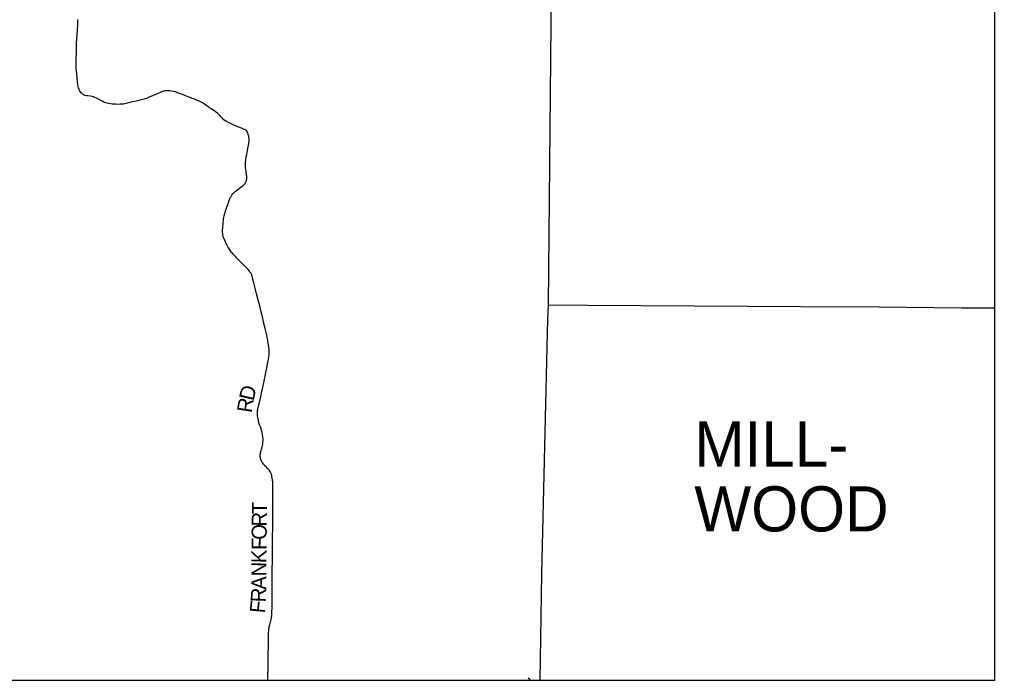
# Model space of a CAD drawing. Extents: x -29.6 to 34, y 0 to 22.
# Drawn here: x -14.201 to -10.748, y 1.053 to 3.392 of the extents above; entities that cross this region are included whole.
import ezdxf

# ---------------------------------------------------------------- set-up
doc = ezdxf.new("R2010")
doc.units = 0
for name, color, linetype in [('GM_X_County_Road', 7, 'Continuous'), ('GM_X_County_Road_Text', 7, 'Continuous'), ('GM_X_Minor_River', 7, 'Continuous'), ('GM_X_Township', 7, 'Continuous'), ('GM_X_Township_Text', 7, 'Continuous'), ('SH_Text', 7, 'Continuous')]:
    doc.layers.add(name, color=color, linetype=linetype)

msp = doc.modelspace()

# ---------------------------------------------------------------- linework, layer by layer
at = {"layer": 'GM_X_County_Road'}
for points in [[(-13.9953, 3.376), (-13.9945, 3.3926)], [(-13.4013, 3.0017), (-13.4052, 3.0035), (-13.4149, 3.0076), (-13.4337, 3.0154), (-13.4492, 3.022), (-13.4588, 3.0263), (-13.4656, 3.0297), (-13.4697, 3.0321), (-13.4731, 3.0343), (-13.4773, 3.0375), (-13.4786, 3.0386), (-13.4828, 3.0427), (-13.4848, 3.0448), (-13.4886, 3.0492), (-13.4919, 3.053), (-13.4938, 3.055), (-13.4976, 3.0584), (-13.5002, 3.0605), (-13.5067, 3.0653), (-13.5081, 3.0663), (-13.5133, 3.0699), (-13.5219, 3.0759), (-13.5243, 3.0775), (-13.5262, 3.0788), (-13.5281, 3.0802), (-13.5305, 3.0818), (-13.5381, 3.0872), (-13.5461, 3.0929), (-13.5529, 3.0973), (-13.5598, 3.1012), (-13.5651, 3.1038), (-13.5679, 3.1049), (-13.5744, 3.1073), (-13.5815, 3.11), (-13.5841, 3.1111), (-13.5852, 3.1116), (-13.5895, 3.1133), (-13.5911, 3.1139), (-13.5921, 3.1142), (-13.6003, 3.1173), (-13.6134, 3.1224), (-13.6177, 3.1241), (-13.6405, 3.1328), (-13.6504, 3.1362), (-13.6559, 3.1378), (-13.6626, 3.1393), (-13.6683, 3.1401), (-13.6735, 3.1403), (-13.6781, 3.1403), (-13.6827, 3.14), (-13.6866, 3.1396), (-13.6915, 3.1383), (-13.7006, 3.1353), (-13.7163, 3.1284), (-13.7258, 3.1242), (-13.7304, 3.1222), (-13.7336, 3.1207), (-13.7415, 3.1172), (-13.7491, 3.1142), (-13.7562, 3.1117), (-13.7641, 3.1094), (-13.7743, 3.1067), (-13.7931, 3.1028), (-13.8015, 3.1007), (-13.81, 3.0986), (-13.8184, 3.0965), (-13.8279, 3.0942), (-13.8331, 3.0933), (-13.8394, 3.0925), (-13.8447, 3.0922), (-13.8546, 3.092), (-13.8616, 3.0922), (-13.8732, 3.0929), (-13.879, 3.0936), (-13.8866, 3.0949), (-13.8911, 3.096), (-13.8973, 3.0979), (-13.9022, 3.0999), (-13.9091, 3.1032), (-13.929, 3.1142), (-13.9342, 3.1167), (-13.939, 3.1185), (-13.9434, 3.1196), (-13.9502, 3.1206), (-13.9588, 3.1217), (-13.9641, 3.1227), (-13.9686, 3.1239), (-13.972, 3.1252), (-13.9746, 3.1266), (-13.9777, 3.1285), (-13.9804, 3.1308), (-13.9829, 3.1334), (-13.9854, 3.1367), (-13.9885, 3.1417), (-13.9905, 3.146), (-13.9919, 3.1499), (-13.9935, 3.1561), (-13.9945, 3.1613), (-13.996, 3.1734), (-13.9986, 3.1999), (-13.9996, 3.2103), (-14.0003, 3.2201), (-14.0005, 3.2276), (-14.0005, 3.2432), (-14.0002, 3.2587), (-13.9999, 3.2703), (-13.9997, 3.2859), (-13.999, 3.3068), (-13.9982, 3.3236), (-13.9974, 3.3387), (-13.9965, 3.3538), (-13.9953, 3.376)], [(-13.4323, 2.5493), (-13.4352, 2.5522), (-13.4444, 2.5619), (-13.4482, 2.5661), (-13.45, 2.5682), (-13.4539, 2.5734), (-13.4581, 2.5795), (-13.4619, 2.5857), (-13.4668, 2.5948), (-13.4712, 2.6036), (-13.4722, 2.6059), (-13.4758, 2.6141), (-13.4778, 2.619), (-13.4785, 2.6209), (-13.4795, 2.6245), (-13.4806, 2.6287), (-13.4815, 2.6339), (-13.4821, 2.6404), (-13.4821, 2.6473), (-13.4816, 2.6554), (-13.4802, 2.6716), (-13.4791, 2.6828), (-13.4782, 2.6886), (-13.4777, 2.6912), (-13.4774, 2.6925), (-13.4762, 2.6979), (-13.4755, 2.7012), (-13.475, 2.703), (-13.4742, 2.7056), (-13.4732, 2.7089), (-13.4724, 2.7114), (-13.4716, 2.714), (-13.4705, 2.7173), (-13.4679, 2.7248), (-13.4664, 2.7291), (-13.465, 2.7332), (-13.4611, 2.7442), (-13.457, 2.755), (-13.4548, 2.7604), (-13.4536, 2.7632), (-13.4527, 2.7652), (-13.4518, 2.767), (-13.4509, 2.7684), (-13.4496, 2.7705), (-13.4486, 2.7722), (-13.4475, 2.7738), (-13.4465, 2.7749), (-13.4454, 2.7761), (-13.4433, 2.7783), (-13.4398, 2.7814), (-13.4364, 2.7843), (-13.4343, 2.786), (-13.4288, 2.7899), (-13.423, 2.7939), (-13.417, 2.7984), (-13.4125, 2.802), (-13.4084, 2.8057), (-13.4056, 2.8084), (-13.4043, 2.8098), (-13.4023, 2.8125), (-13.4005, 2.8154), (-13.3998, 2.8168), (-13.3989, 2.8191), (-13.3982, 2.8208), (-13.3975, 2.8228), (-13.397, 2.8251), (-13.3966, 2.8268), (-13.3963, 2.8304), (-13.3962, 2.8333), (-13.3964, 2.8381), (-13.3968, 2.8416), (-13.399, 2.8547), (-13.4, 2.8616), (-13.4005, 2.8667), (-13.4008, 2.8708), (-13.4009, 2.876), (-13.401, 2.88), (-13.4007, 2.8846), (-13.4003, 2.8897), (-13.3998, 2.8937), (-13.3993, 2.8978), (-13.3985, 2.9031), (-13.3981, 2.9058), (-13.3965, 2.9143), (-13.3951, 2.9213), (-13.3938, 2.9282), (-13.3923, 2.9362), (-13.3911, 2.9423), (-13.3901, 2.948), (-13.3889, 2.9538), (-13.3886, 2.9562), (-13.3882, 2.9601), (-13.3881, 2.9665), (-13.3884, 2.9714), (-13.389, 2.9766), (-13.3895, 2.9804), (-13.3899, 2.9822), (-13.391, 2.9859), (-13.3928, 2.9911), (-13.3944, 2.995), (-13.3952, 2.9966), (-13.3959, 2.9976), (-13.3966, 2.9984), (-13.3977, 2.9994), (-13.3994, 3.0007), (-13.4013, 3.0017)], [(-13.3801, 2.4913), (-13.3811, 2.4932), (-13.3825, 2.4956), (-13.3838, 2.4975), (-13.3852, 2.4994), (-13.3872, 2.5018), (-13.3918, 2.507), (-13.3976, 2.5131), (-13.4078, 2.5238), (-13.4197, 2.5363), (-13.4286, 2.5455), (-13.4323, 2.5493)], [(-13.3327, 1.8132), (-13.3367, 1.8183), (-13.3394, 1.8217), (-13.3419, 1.8254), (-13.3433, 1.8278), (-13.3438, 1.8286), (-13.3441, 1.8293), (-13.3444, 1.8298), (-13.3451, 1.8313), (-13.3465, 1.8348), (-13.3473, 1.8376), (-13.3478, 1.8399), (-13.3482, 1.8424), (-13.3485, 1.8458), (-13.3486, 1.8492), (-13.3485, 1.8518), (-13.3483, 1.8547), (-13.3477, 1.8585), (-13.3473, 1.8603), (-13.3465, 1.8636), (-13.3457, 1.8664), (-13.344, 1.8721), (-13.343, 1.8755), (-13.3427, 1.8766), (-13.3417, 1.8805), (-13.341, 1.8833), (-13.3407, 1.885), (-13.3398, 1.8896), (-13.3392, 1.8936), (-13.339, 1.8969), (-13.3387, 1.9024), (-13.3387, 1.9055), (-13.3387, 1.9078), (-13.3388, 1.9098), (-13.3394, 1.9161), (-13.3401, 1.9214), (-13.3408, 1.9252), (-13.343, 1.9341), (-13.3438, 1.9367), (-13.3457, 1.9433), (-13.3483, 1.9507), (-13.3508, 1.9581), (-13.3532, 1.9653), (-13.3538, 1.9671), (-13.3545, 1.97), (-13.3552, 1.9731), (-13.3564, 1.979), (-13.3571, 1.9837), (-13.3578, 1.99), (-13.3581, 1.9948), (-13.3582, 1.9974), (-13.3582, 1.9995), (-13.3582, 2.003), (-13.3578, 2.0081), (-13.3573, 2.0116), (-13.3569, 2.0147), (-13.356, 2.0187), (-13.3548, 2.0235), (-13.3525, 2.0324), (-13.3482, 2.0526), (-13.3457, 2.0642), (-13.3427, 2.0766), (-13.3409, 2.0834), (-13.3377, 2.0969), (-13.3355, 2.1067), (-13.3331, 2.1189), (-13.331, 2.129), (-13.3295, 2.1369), (-13.3252, 2.1597), (-13.3225, 2.1729), (-13.3196, 2.1895), (-13.3182, 2.1988), (-13.3175, 2.2052), (-13.3173, 2.2081), (-13.317, 2.2175), (-13.3172, 2.2238), (-13.3181, 2.2331), (-13.3193, 2.2411), (-13.3216, 2.2537), (-13.3223, 2.2575), (-13.3242, 2.2673), (-13.3268, 2.2797), (-13.3312, 2.2988), (-13.3366, 2.3217), (-13.34, 2.3351), (-13.3455, 2.3582), (-13.3505, 2.3785), (-13.357, 2.4038), (-13.3616, 2.4212), (-13.3655, 2.4364), (-13.3681, 2.4465), (-13.3693, 2.4508), (-13.3705, 2.4553), (-13.3716, 2.4599), (-13.3726, 2.464), (-13.3747, 2.472), (-13.3766, 2.4799), (-13.3781, 2.4858), (-13.379, 2.4886), (-13.3801, 2.4913)], [(-13.3218, 1.0528), (-13.3215, 1.0623), (-13.3213, 1.071), (-13.3208, 1.0943), (-13.3208, 1.103), (-13.3206, 1.1112), (-13.3204, 1.1222), (-13.3205, 1.1292), (-13.3203, 1.1403), (-13.32, 1.1507), (-13.3198, 1.1725), (-13.3194, 1.1933), (-13.3192, 1.2122), (-13.3188, 1.2217), (-13.3183, 1.2308), (-13.3178, 1.2351), (-13.3174, 1.2382), (-13.3166, 1.2424), (-13.3147, 1.2503), (-13.3111, 1.2644), (-13.309, 1.2736), (-13.3083, 1.2779), (-13.3079, 1.2806), (-13.3075, 1.2858), (-13.307, 1.2961), (-13.3066, 1.3094), (-13.3066, 1.3211), (-13.3066, 1.3376), (-13.3064, 1.3545), (-13.3062, 1.3755), (-13.3061, 1.3871), (-13.3061, 1.4034), (-13.306, 1.4179), (-13.306, 1.4329), (-13.3059, 1.4429), (-13.3057, 1.4773), (-13.3057, 1.5012), (-13.3058, 1.5116), (-13.3056, 1.5294), (-13.3053, 1.5436), (-13.305, 1.5596), (-13.3048, 1.5696), (-13.3045, 1.5866), (-13.3043, 1.5992), (-13.3041, 1.6163), (-13.3042, 1.6277), (-13.3044, 1.6377), (-13.3043, 1.6498), (-13.304, 1.6756), (-13.304, 1.6902), (-13.3038, 1.7013), (-13.3038, 1.7105), (-13.3037, 1.7216), (-13.3038, 1.7356), (-13.3039, 1.7436), (-13.3041, 1.7467), (-13.3045, 1.7542), (-13.3053, 1.7625), (-13.3062, 1.7695), (-13.3072, 1.7755), (-13.3075, 1.7774), (-13.308, 1.7795), (-13.3085, 1.7813), (-13.3091, 1.7832), (-13.3099, 1.7854), (-13.3111, 1.788), (-13.3118, 1.7894), (-13.3125, 1.7905), (-13.3134, 1.7921), (-13.3157, 1.7956), (-13.318, 1.7986), (-13.3196, 1.8005), (-13.3216, 1.8025), (-13.3242, 1.8049), (-13.3269, 1.8074), (-13.3319, 1.8123), (-13.3327, 1.8132)]]:
    msp.add_lwpolyline(points, dxfattribs=at)
at = {"layer": 'GM_X_Minor_River'}
msp.add_lwpolyline([(-12.3923, 1.0528), (-12.394, 1.0558), (-12.3997, 1.0611)], dxfattribs=at)
at = {"layer": 'GM_X_Township'}
for points in [[(-10.7478, 7.0493), (-10.7917, 7.05), (-10.9427, 7.0551), (-11.0852, 7.0579), (-12.1902, 7.0754), (-12.2612, 7.0767), (-12.2665, 6.8423), (-12.2783, 6.2218), (-12.2845, 5.982), (-12.2945, 5.335), (-12.2964, 5.2867), (-12.3049, 4.8179), (-12.3049, 4.755), (-12.3046, 4.7346), (-12.3198, 3.3777), (-12.3286, 2.3826), (-12.1886, 2.3813), (-11.4346, 2.3766), (-11.1566, 2.3751), (-10.8647, 2.3724), (-10.7478, 2.3716)], [(-12.3286, 2.3826), (-12.331, 2.3321), (-12.3521, 1.4305), (-12.3586, 1.0528)]]:
    msp.add_lwpolyline(points, dxfattribs=at)
at = {"layer": 'SH_Text'}
msp.add_lwpolyline([(-29.5833, 13.2079), (-10.7478, 13.2079), (-10.7478, 1.0528), (-29.5833, 1.0528)], close=True, dxfattribs=at)

# ---------------------------------------------------------------- texts
at = {"layer": 'GM_X_County_Road_Text'}
for s, rotation, p in [('D', 76.9074, (-13.3725, 2.0404)), ('R', 81.4835, (-13.3788, 1.9983)), ('T', 89.4857, (-13.3251, 1.6413)), ('R', 89.4878, (-13.3255, 1.5976)), ('O', 89.4827, (-13.326, 1.5507)), ('F', 89.4868, (-13.3263, 1.5147)), ('K', 89.4864, (-13.3267, 1.4679)), ('N', 89.4857, (-13.3271, 1.421)), ('A', 89.4143, (-13.3276, 1.3741)), ('R', 87.6617, (-13.3294, 1.3286)), ('F', 84.3603, (-13.3332, 1.2895))]:
    msp.add_text(s, height=0.0533, rotation=rotation, dxfattribs=at).set_placement(p)
at = {"layer": 'GM_X_Township_Text'}
for s, p in [('MILL-', (-11.8113, 1.8101)), ('WOOD', (-11.8113, 1.5803))]:
    msp.add_text(s, height=0.1598, rotation=0, dxfattribs=at).set_placement(p)

doc.saveas('drawing.dxf')
